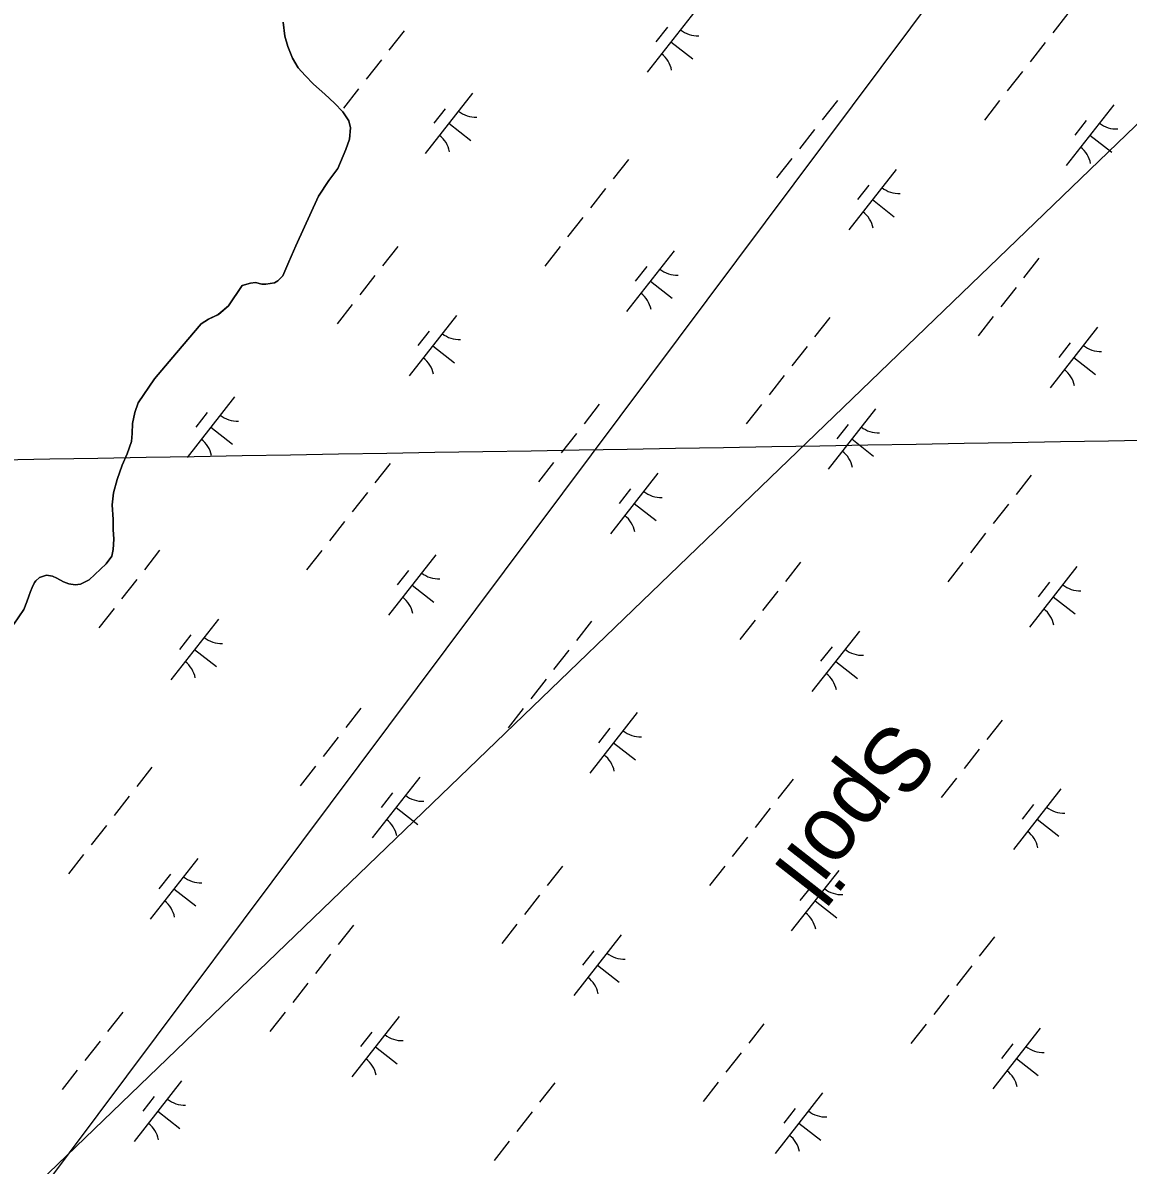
# Model space of a CAD drawing. Extents: x 3896831 to 3918110, y 171006 to 193349.
# Drawn here: x 3910415 to 3911133, y 186792 to 187534 of the extents above; entities that cross this region are included whole.
import ezdxf

# ---------------------------------------------------------------- set-up
doc = ezdxf.new("R2010")
doc.units = 0
for name, color, linetype in [('V-CHAN-SPOL', 7, 'Continuous'), ('V-GRID-MAJR', 7, 'Continuous'), ('V-TOPO-SHOR', 7, 'Continuous'), ('V-UTIL-LINE', 7, 'Continuous'), ('V-WETL-SWMP', 7, 'Continuous')]:
    doc.layers.add(name, color=color, linetype=linetype)

msp = doc.modelspace()

# ---------------------------------------------------------------- linework, layer by layer
at = {"layer": 'V-GRID-MAJR'}
msp.add_spline([(3906725.43, 187187.12), (3909556.5, 187235.56), (3913560.29, 187304.5)], degree=3, dxfattribs=at)
at = {"layer": 'V-TOPO-SHOR'}
for points in [[(3910580.63, 187366.43), (3910583.79, 187369.61), (3910587.6, 187378.72), (3910592.2, 187389.15), (3910607.07, 187421.37), (3910613.78, 187431.55), (3910619.44, 187439.47), (3910624.83, 187451.75), (3910627.07, 187458.49), (3910627.71, 187465.88), (3910626.65, 187470.36), (3910622.82, 187476.3), (3910617.4, 187481.83), (3910611.19, 187487.76), (3910603.65, 187494.21), (3910598.23, 187499.88), (3910593.74, 187504.89), (3910590.03, 187511.08), (3910586.99, 187518.73), (3910585.13, 187525.46), (3910583.93, 187534.43)], [(3910408.89, 187143.27), (3910415.48, 187152.78), (3910417.45, 187157.67), (3910418.76, 187161.36), (3910419.81, 187164.53), (3910420.87, 187167.04), (3910422.31, 187170.21), (3910423.23, 187171.27), (3910425.74, 187173.52), (3910430.09, 187175.11), (3910434.05, 187174.45), (3910436.96, 187173.01), (3910441.18, 187170.64), (3910444.62, 187169.32), (3910448.84, 187168.67), (3910452.27, 187169.21), (3910454.12, 187170), (3910457.94, 187171.98), (3910468.88, 187182.43), (3910472.7, 187187.32), (3910473.48, 187191.67), (3910473.87, 187198.4), (3910473.46, 187204.74), (3910473.45, 187211.33), (3910472.77, 187220.83), (3910473.82, 187228.62), (3910476.18, 187237.34), (3910479.33, 187246.45), (3910482.62, 187253.84), (3910485.51, 187262.03), (3910485.9, 187267.18), (3910486.15, 187273.64), (3910487.59, 187280.9), (3910489.83, 187287.11), (3910500.36, 187302.7), (3910514.72, 187319.48), (3910530.66, 187338.51), (3910535.53, 187341.55), (3910541.87, 187344.46), (3910548.58, 187350.02), (3910557.41, 187363.36), (3910562.81, 187364.95), (3910566.11, 187365.22), (3910570.07, 187364.31), (3910572.71, 187364.31), (3910578.39, 187364.98), (3910580.63, 187366.43)]]:
    msp.add_lwpolyline(points, dxfattribs=at)
at = {"layer": 'V-UTIL-LINE'}
for points in [[(3907581.38, 183502.32), (3907734.57, 183396.26), (3908170.58, 183973.68), (3908524.1, 184327.21), (3908912.98, 184727.87), (3909396.13, 185399.56), (3909513.97, 185670.6), (3909808.57, 186000.55), (3910067.82, 186295.15), (3911010.55, 187556.05), (3911470.13, 188145.26)], [(3911670.46, 187980.28), (3909726.08, 186106.61), (3909690.73, 186047.69), (3909490.4, 185423.13), (3908571.24, 184256.5), (3908123.44, 183643.73), (3907157.15, 182394.62), (3906544.37, 181593.3), (3906120.15, 181051.23), (3905460.24, 180002.44), (3904670.7, 178765.11), (3903951.87, 177622.05), (3903445.16, 176832.52), (3902962.01, 176054.77), (3902855.95, 175866.22)]]:
    msp.add_lwpolyline(points, dxfattribs=at)
at = {"layer": 'V-WETL-SWMP'}
for p, q in [((3910851.49, 187541.42), (3910820.65, 187502.07)), ((3911094.08, 187540.16), (3911084.21, 187527.57)), ((3910583.93, 187534.43), (3910585.13, 187525.46)), ((3910585.13, 187525.46), (3910586.99, 187518.73)), ((3910662.63, 187528.98), (3910652.76, 187516.38)), ((3910833.7, 187531.23), (3910826.29, 187521.78)), ((3910586.99, 187518.73), (3910590.03, 187511.08)), ((3910836.07, 187521.74), (3910850.24, 187510.64)), ((3911079.28, 187521.28), (3911069.41, 187508.68)), ((3910590.03, 187511.08), (3910593.74, 187504.89)), ((3910593.74, 187504.89), (3910598.23, 187499.88)), ((3910647.83, 187510.09), (3910637.96, 187497.49)), ((3910598.23, 187499.88), (3910603.65, 187494.21)), ((3911064.47, 187502.39), (3911054.6, 187489.79)), ((3910603.65, 187494.21), (3910611.19, 187487.76)), ((3910633.02, 187491.2), (3910623.15, 187478.6)), ((3910707.16, 187488.46), (3910676.31, 187449.11)), ((3910611.19, 187487.76), (3910617.4, 187481.83)), ((3910617.4, 187481.83), (3910622.82, 187476.3)), ((3910944.2, 187483.63), (3910934.33, 187471.03)), ((3911049.67, 187483.5), (3911039.8, 187470.9)), ((3911123.8, 187480.76), (3911092.96, 187441.41)), ((3910622.82, 187476.3), (3910626.65, 187470.36)), ((3910689.36, 187478.27), (3910681.96, 187468.82)), ((3910626.65, 187470.36), (3910627.71, 187465.88)), ((3910627.71, 187465.88), (3910627.07, 187458.49)), ((3910691.73, 187468.78), (3910705.9, 187457.68)), ((3911106.01, 187470.57), (3911098.6, 187461.12)), ((3910627.07, 187458.49), (3910624.83, 187451.75)), ((3910929.4, 187464.74), (3910919.53, 187452.14)), ((3911108.38, 187461.08), (3911122.54, 187449.98)), ((3910624.83, 187451.75), (3910619.44, 187439.47)), ((3910808.36, 187445.26), (3910798.49, 187432.66)), ((3910914.59, 187445.85), (3910904.72, 187433.25)), ((3910619.44, 187439.47), (3910613.78, 187431.54)), ((3910982.41, 187438.81), (3910951.57, 187399.46)), ((3910613.78, 187431.54), (3910607.07, 187421.37)), ((3910964.62, 187428.62), (3910957.21, 187419.17)), ((3910607.07, 187421.37), (3910592.21, 187389.15)), ((3910793.55, 187426.37), (3910783.68, 187413.77)), ((3910966.99, 187419.14), (3910981.15, 187408.03)), ((3910778.75, 187407.48), (3910768.88, 187394.88)), ((3910592.21, 187389.15), (3910587.6, 187378.72)), ((3910658.48, 187388.72), (3910648.61, 187376.13)), ((3910763.94, 187388.59), (3910754.07, 187375.99)), ((3910838.08, 187385.85), (3910807.23, 187346.5)), ((3910587.6, 187378.72), (3910583.79, 187369.61)), ((3911075.12, 187381.02), (3911065.25, 187368.43)), ((3910583.79, 187369.61), (3910580.63, 187366.43)), ((3910643.67, 187369.83), (3910633.8, 187357.24)), ((3910820.28, 187375.66), (3910812.88, 187366.21)), ((3910557.41, 187363.36), (3910548.58, 187350.02)), ((3910562.81, 187364.95), (3910557.41, 187363.36)), ((3910566.11, 187365.22), (3910562.81, 187364.95)), ((3910570.07, 187364.3), (3910566.11, 187365.22)), ((3910572.71, 187364.31), (3910570.07, 187364.3)), ((3910578.39, 187364.98), (3910572.71, 187364.31)), ((3910580.63, 187366.43), (3910578.39, 187364.98)), ((3910822.65, 187366.18), (3910836.82, 187355.07)), ((3911060.32, 187362.13), (3911050.45, 187349.54)), ((3910548.58, 187350.02), (3910541.86, 187344.46)), ((3910628.87, 187350.94), (3910619, 187338.35)), ((3910535.53, 187341.55), (3910530.66, 187338.51)), ((3910541.86, 187344.46), (3910535.53, 187341.55)), ((3910696.68, 187343.9), (3910665.84, 187304.55)), ((3910939.27, 187342.65), (3910929.4, 187330.05)), ((3911045.51, 187343.24), (3911035.64, 187330.65)), ((3910530.66, 187338.51), (3910514.72, 187319.48)), ((3910678.89, 187333.71), (3910671.49, 187324.26)), ((3911113.33, 187336.2), (3911082.48, 187296.85)), ((3911095.53, 187326.01), (3911088.13, 187316.56)), ((3910514.72, 187319.48), (3910500.36, 187302.7)), ((3910681.26, 187324.23), (3910695.43, 187313.12)), ((3910924.47, 187323.76), (3910914.6, 187311.17)), ((3911097.91, 187316.53), (3911112.07, 187305.42)), ((3910500.36, 187302.7), (3910489.83, 187287.11)), ((3910909.66, 187304.87), (3910899.79, 187292.28)), ((3910552.35, 187290.94), (3910521.51, 187251.59)), ((3910487.59, 187280.9), (3910486.15, 187273.64)), ((3910489.83, 187287.11), (3910487.59, 187280.9)), ((3910534.56, 187280.75), (3910527.16, 187271.3)), ((3910789.4, 187286.11), (3910779.53, 187273.52)), ((3910894.86, 187285.98), (3910884.99, 187273.39)), ((3910968.99, 187283.24), (3910938.15, 187243.89)), ((3910486.15, 187273.64), (3910485.9, 187267.18)), ((3910951.2, 187273.05), (3910943.8, 187263.6)), ((3910485.9, 187267.18), (3910485.51, 187262.03)), ((3910536.93, 187271.27), (3910551.1, 187260.16)), ((3910774.59, 187267.22), (3910764.72, 187254.63)), ((3910485.51, 187262.03), (3910482.62, 187253.84)), ((3910953.57, 187263.57), (3910967.74, 187252.46)), ((3910482.62, 187253.84), (3910479.33, 187246.45)), ((3910479.33, 187246.45), (3910476.18, 187237.34)), ((3910653.55, 187247.74), (3910643.68, 187235.15)), ((3910759.79, 187248.33), (3910749.92, 187235.74)), ((3910476.18, 187237.34), (3910473.82, 187228.62)), ((3910827.6, 187241.29), (3910796.76, 187201.94)), ((3911070.19, 187240.04), (3911060.32, 187227.45)), ((3910473.82, 187228.62), (3910472.78, 187220.84)), ((3910638.75, 187228.85), (3910628.88, 187216.26)), ((3910809.81, 187231.1), (3910802.41, 187221.66)), ((3910472.78, 187220.84), (3910473.45, 187211.33)), ((3910812.18, 187221.62), (3910826.35, 187210.51)), ((3911055.39, 187221.15), (3911045.52, 187208.56)), ((3910473.45, 187211.33), (3910473.46, 187204.74)), ((3910623.94, 187209.96), (3910614.07, 187197.37)), ((3910473.46, 187204.74), (3910473.87, 187198.4)), ((3910473.87, 187198.4), (3910473.48, 187191.67)), ((3911040.58, 187202.26), (3911030.71, 187189.67)), ((3910473.48, 187191.67), (3910472.7, 187187.32)), ((3910503.67, 187191.2), (3910493.8, 187178.61)), ((3910609.14, 187191.07), (3910599.27, 187178.48)), ((3910472.7, 187187.32), (3910468.88, 187182.43)), ((3910683.27, 187188.33), (3910652.43, 187148.98)), ((3910468.88, 187182.43), (3910457.94, 187171.98)), ((3910665.48, 187178.14), (3910658.07, 187168.7)), ((3910920.32, 187183.5), (3910910.45, 187170.91)), ((3911025.78, 187183.37), (3911015.91, 187170.78)), ((3911099.91, 187180.64), (3911069.07, 187141.28)), ((3910422.31, 187170.21), (3910420.87, 187167.04)), ((3910423.23, 187171.27), (3910422.31, 187170.21)), ((3910425.74, 187173.52), (3910423.23, 187171.27)), ((3910430.09, 187175.11), (3910425.74, 187173.52)), ((3910434.05, 187174.45), (3910430.09, 187175.11)), ((3910436.96, 187173.01), (3910434.05, 187174.45)), ((3910441.18, 187170.64), (3910436.96, 187173.01)), ((3910444.62, 187169.32), (3910441.18, 187170.64)), ((3910448.84, 187168.67), (3910444.62, 187169.32)), ((3910452.27, 187169.2), (3910448.84, 187168.67)), ((3910454.12, 187170), (3910452.27, 187169.2)), ((3910457.94, 187171.98), (3910454.12, 187170)), ((3910488.87, 187172.31), (3910479, 187159.72)), ((3911082.12, 187170.44), (3911074.72, 187161)), ((3910418.76, 187161.37), (3910417.45, 187157.67)), ((3910419.81, 187164.53), (3910418.76, 187161.37)), ((3910420.87, 187167.04), (3910419.81, 187164.53)), ((3910667.85, 187168.66), (3910682.01, 187157.55)), ((3910905.51, 187164.61), (3910895.64, 187152.02)), ((3910417.45, 187157.67), (3910415.48, 187152.78)), ((3911084.49, 187160.96), (3911098.66, 187149.85)), ((3910415.48, 187152.78), (3910408.89, 187143.27)), ((3910474.06, 187153.42), (3910464.19, 187140.83)), ((3910541.88, 187146.39), (3910511.04, 187107.03)), ((3910784.47, 187145.13), (3910774.6, 187132.54)), ((3910890.71, 187145.72), (3910880.84, 187133.13)), ((3910524.09, 187136.19), (3910516.68, 187126.75)), ((3910958.52, 187138.69), (3910927.68, 187099.33)), ((3910526.46, 187126.71), (3910540.62, 187115.61)), ((3910769.66, 187126.24), (3910759.79, 187113.65)), ((3910940.73, 187128.49), (3910933.33, 187119.05)), ((3910943.1, 187119.01), (3910957.27, 187107.91)), ((3910754.86, 187107.35), (3910744.99, 187094.76)), ((3910634.59, 187088.59), (3910624.72, 187076)), ((3910740.05, 187088.46), (3910730.18, 187075.87)), ((3910814.19, 187085.73), (3910783.34, 187046.37)), ((3911051.23, 187080.89), (3911041.36, 187068.3)), ((3910796.39, 187075.53), (3910788.99, 187066.09)), ((3910619.79, 187069.7), (3910609.92, 187057.11)), ((3910798.77, 187066.05), (3910812.93, 187054.95)), ((3911036.43, 187062), (3911026.56, 187049.41)), ((3910498.74, 187050.22), (3910488.87, 187037.63)), ((3910604.98, 187050.81), (3910595.11, 187038.22)), ((3910672.8, 187043.78), (3910641.95, 187004.42)), ((3910915.39, 187042.52), (3910905.52, 187029.93)), ((3911021.62, 187043.11), (3911011.75, 187030.52)), ((3911089.44, 187036.08), (3911058.6, 186996.72)), ((3910483.94, 187031.33), (3910474.07, 187018.74)), ((3910655, 187033.58), (3910647.6, 187024.14)), ((3910657.38, 187024.1), (3910671.54, 187013)), ((3910900.58, 187023.63), (3910890.71, 187011.04)), ((3911071.65, 187025.88), (3911064.24, 187016.44)), ((3911074.02, 187016.4), (3911088.19, 187005.3)), ((3910469.13, 187012.44), (3910459.26, 186999.85)), ((3910885.78, 187004.74), (3910875.91, 186992.15)), ((3910454.33, 186993.55), (3910444.46, 186980.96)), ((3910528.46, 186990.82), (3910497.62, 186951.46)), ((3910765.51, 186985.98), (3910755.64, 186973.39)), ((3910870.97, 186985.85), (3910861.1, 186973.26)), ((3910945.11, 186983.12), (3910914.26, 186943.76)), ((3910510.67, 186980.62), (3910503.27, 186971.18)), ((3910513.04, 186971.14), (3910527.21, 186960.04)), ((3910927.31, 186972.92), (3910919.91, 186963.48)), ((3910750.7, 186967.09), (3910740.83, 186954.5)), ((3910929.68, 186963.44), (3910943.85, 186952.34)), ((3910629.66, 186947.61), (3910619.79, 186935.02)), ((3910735.9, 186948.2), (3910726.03, 186935.61)), ((3910803.72, 186941.17), (3910772.87, 186901.82)), ((3911046.31, 186939.91), (3911036.44, 186927.32)), ((3910614.86, 186928.72), (3910604.99, 186916.13)), ((3910785.92, 186930.97), (3910778.52, 186921.53)), ((3910788.29, 186921.49), (3910802.46, 186910.39)), ((3911031.5, 186921.02), (3911021.63, 186908.43)), ((3910600.05, 186909.83), (3910590.18, 186897.24)), ((3911016.7, 186902.13), (3911006.83, 186889.54)), ((3910479.78, 186891.08), (3910469.91, 186878.48)), ((3910585.25, 186890.94), (3910575.38, 186878.35)), ((3910659.38, 186888.21), (3910628.54, 186848.86)), ((3910896.43, 186883.38), (3910886.56, 186870.78)), ((3911001.89, 186883.24), (3910992.02, 186870.65)), ((3911076.02, 186880.51), (3911045.18, 186841.16)), ((3910464.98, 186872.19), (3910455.11, 186859.59)), ((3910641.59, 186878.01), (3910634.19, 186868.57)), ((3910643.96, 186868.53), (3910658.13, 186857.43)), ((3910881.62, 186864.49), (3910871.75, 186851.89)), ((3911058.23, 186870.31), (3911050.83, 186860.87)), ((3911060.6, 186860.83), (3911074.77, 186849.73)), ((3910450.18, 186853.3), (3910440.31, 186840.7)), ((3910517.99, 186846.26), (3910487.15, 186806.91)), ((3910760.58, 186845), (3910750.71, 186832.41)), ((3910866.82, 186845.6), (3910856.95, 186833)), ((3910500.2, 186836.07), (3910492.8, 186826.62)), ((3910934.63, 186838.56), (3910903.79, 186799.21)), ((3910916.84, 186828.37), (3910909.44, 186818.92)), ((3910502.57, 186826.58), (3910516.74, 186815.48)), ((3910745.78, 186826.12), (3910735.91, 186813.52)), ((3910919.21, 186818.88), (3910933.38, 186807.78)), ((3910730.97, 186807.23), (3910721.1, 186794.63))]:
    msp.add_line(p, q, dxfattribs=at)
for centre, start, end in [((3910853.29, 187543.34), 231.14028, 272.68394), ((3910819.22, 187499.86), 11.14028, 52.68394), ((3910708.96, 187490.38), 231.14028, 272.68394), ((3911125.6, 187482.68), 231.14028, 272.68394), ((3910674.88, 187446.9), 11.14028, 52.68394), ((3911091.53, 187439.2), 11.14028, 52.68394), ((3910984.21, 187440.73), 231.14028, 272.68394), ((3910950.14, 187397.25), 11.14028, 52.68394), ((3910839.88, 187387.77), 231.14028, 272.68394), ((3910805.8, 187344.29), 11.14028, 52.68394), ((3910698.49, 187345.82), 231.14028, 272.68394), ((3911115.13, 187338.12), 231.14028, 272.68394), ((3910664.41, 187302.34), 11.14028, 52.68394), ((3911081.05, 187294.64), 11.14028, 52.68394), ((3910554.15, 187292.86), 231.14028, 272.68394), ((3910970.8, 187285.16), 231.14028, 272.68394), ((3910520.08, 187249.38), 11.14028, 52.68394), ((3910936.72, 187241.68), 11.14028, 52.68394), ((3910829.41, 187243.21), 231.14028, 272.68394), ((3910795.33, 187199.73), 11.14028, 52.68394), ((3910685.07, 187190.25), 231.14028, 272.68394), ((3911101.72, 187182.55), 231.14028, 272.68394), ((3910651, 187146.77), 11.14028, 52.68394), ((3911067.64, 187139.07), 11.14028, 52.68394), ((3910543.68, 187148.3), 231.14028, 272.68394), ((3910960.33, 187140.6), 231.14028, 272.68394), ((3910509.6, 187104.82), 11.14028, 52.68394), ((3910926.25, 187097.12), 11.14028, 52.68394), ((3910815.99, 187087.64), 231.14028, 272.68394), ((3910781.91, 187044.16), 11.14028, 52.68394), ((3910674.6, 187045.69), 231.14028, 272.68394), ((3911091.24, 187037.99), 231.14028, 272.68394), ((3910640.52, 187002.21), 11.14028, 52.68394), ((3911057.17, 186994.51), 11.14028, 52.68394), ((3910530.27, 186992.73), 231.14028, 272.68394), ((3910946.91, 186985.03), 231.14028, 272.68394), ((3910496.19, 186949.25), 11.14028, 52.68394), ((3910912.83, 186941.55), 11.14028, 52.68394), ((3910805.52, 186943.09), 231.14028, 272.68394), ((3910771.44, 186899.61), 11.14028, 52.68394), ((3910661.19, 186890.13), 231.14028, 272.68394), ((3911077.83, 186882.43), 231.14028, 272.68394), ((3910627.11, 186846.65), 11.14028, 52.68394), ((3911043.75, 186838.95), 11.14028, 52.68394), ((3910519.8, 186848.18), 231.14028, 272.68394), ((3910936.44, 186840.48), 231.14028, 272.68394), ((3910485.72, 186804.7), 11.14028, 52.68394), ((3910902.36, 186797), 11.14028, 52.68394)]:
    msp.add_arc(centre, 17.62, start, end, dxfattribs=at)

# ---------------------------------------------------------------- texts
at = {"layer": 'V-CHAN-SPOL'}
msp.add_text('Spoil', height=42, rotation=231.90858, dxfattribs=at).set_placement((3910978.58, 187082.67))

doc.saveas('drawing.dxf')
